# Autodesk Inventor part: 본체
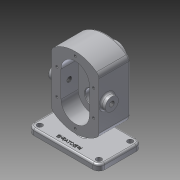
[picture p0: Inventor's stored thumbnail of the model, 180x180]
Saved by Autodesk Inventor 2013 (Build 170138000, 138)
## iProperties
Created: 2019-03
Part Number: 본체
Material: 알루미늄 6061
Document SubType Name: Modeling
Designer: Administrator
Density: 2.71 g/cm^3
Mass: 1193.14 g
Surface Area: 720.724 cm^2
Volume: 440.275 cm^3
Author: Administrator
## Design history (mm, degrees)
sketch "스케치2"
  geometry: L1 (-40, 60)-(40, 60); L2 (40, 60)-(40, -60); L3 (40, -60)-(-40, -60); L4 (-40, -60)-(-40, 60); A1 r 60 centre (0, 0) between (-40, -44.721) and (40, -44.721); A2 r 60 centre (0, 0) between (40, 44.721) and (-40, 44.721); 3 further points
  constraints: 8 end point, 5 point on circle, 4 point on line, 2 centre point, 2 midpoint, 2 parallel, 1 coincident, 1 horizontal, 1 horizontal alignment, 1 perpendicular, 1 vertical alignment
  dimensions: "d0" = 80 distance between parallel lines of L2 L4; "d2" = 120 distance of L3.end L1.start; "d5" = 60 radius of A2; "d6" = 60 radius of A1
extrude "돌출1" new body sketch "스케치2" distance "d7" = 53; taper "d8" = 0 deg
sketch "스케치3"
  geometry: L1 (-40, 44.721)-(-40, -44.721) reference; L2 (-24, 22)-(-24, -22); L3 (24, -22)-(24, 22); A1 r 60 centre (0, 0) between (40, 44.721) and (-40, 44.721) reference; A2 r 24 centre (0, 22) between (24, 22) and (-24, 22); A3 r 24 centre (0, -22) between (-24, -22) and (24, -22)
  constraints: 4 end point, 4 point on circle, 2 centre point, 2 parallel, 2 tangent, 2 vertical alignment
  dimensions: "d9" = 24 radius of A2; "d10" = 24 radius of A3; "d11" = 44 distance of A3.centre A2.centre; "d12" = 22 distance of A1.centre A2.centre
extrude "돌출2" cut sketch "스케치3" distance "d13" = 29; taper "d14" = 0 deg
sketch "스케치4"
  geometry: C1 r 12.5 at (0, 22); C2 r 12.5 at (0, -22); A1 r 24 centre (0, -22) between (-24, -22) and (24, -22) reference; A2 r 24 centre (0, 22) between (24, 22) and (-24, 22) reference; 1 further point
  constraints: 2 centre point, 2 coincident
  dimensions: "d15" = 12.5 radius of C1; "d16" = 12.5 radius of C2
extrude "돌출3" cut sketch "스케치4" distance "d17" = 15; taper "d18" = 0 deg
sketch "스케치5"
  geometry: C1 r 12.5 at (0, 0) reference; C2 r 8.5 at (0, 0); 1 further point
  constraints: 1 centre point, 1 coincident
  dimensions: "d19" = 8.5 radius of C2
extrude "돌출4" cut sketch "스케치5" stored distance "d20" = 15; taper "d21" = 0 deg
sketch "스케치6"
  geometry: C1 r 8.5 at (0, 22) reference; C2 r 19 at (0, 22)
  constraints: 1 centre point, 1 coincident
  dimensions: "d22" = 19 radius of C2
extrude "돌출5" join sketch "스케치6" distance "d23" = 17; taper "d24" = 0 deg
sketch "스케치7"
  geometry: L1 (3, -17)-(41, -17) reference; L2 (30.5, 9)-(30.5, -17) reference; L3 (13.5, 9)-(13.5, -17) reference; L4 (22, 8.572)-(22, -17); L5 (22, -9.7)-(35.5, -9.7); L6 (36, -10.2)-(36, -16.3); L7 (36, -16.3)-(22, -16.3); L8 (22, -16.3)-(22, -9.7); L9 (36, -16.3)-(36.404, -17); L10 (36, -16.3)-(39.088, -16.3); L11 (36, -16.3)-(36, -19.794); A1 r 0.5 centre (35.5, -10.2) between (36, -10.2) and (35.5, -9.7); 2 further points
  constraints: 16 end point, 4 point on line, 3 parallel, 2 horizontal, 2 perpendicular, 2 point on circle, 2 tangent, 1 centre point, 1 midpoint
  dimensions: "d25" = 6.6 distance of point (36, -9.7) L6.end; "d28" = 7.3 distance from line of L4.end L5; "d30" = 28 diameter of L6 L4; "d31" = 30 deg angle of L11 L9; "d32" = 0.5 radius of A1
revolve "회전1" sketch "스케치7" stored, may be unused: angle "d33" = 90 deg
sketch "스케치8"
  geometry: C1 r 12.5 at (0, 22) reference; A1 r 24 centre (0, -22) between (-24, -22) and (24, -22) reference; A2 r 24 centre (0, 22) between (24, 22) and (-24, 22) reference; A3 r 31 centre (0, 22) between (0, 53) and (-31, 22); A4 r 31 centre (0, -22) between (31, -22) and (0, -53); 2 further points
  constraints: 6 point on circle, 4 vertical alignment, 2 centre point, 2 coincident, 2 horizontal alignment
  dimensions: "d34" = 31 radius of A3; "d35" = 31 radius of A4
hole "구멍1" sketch "스케치8" at (0, 53), (-31, 22), (31, 22), (31, -22), (0, -53), (-31, -22) diameter "d36" = 4.134; stored, may be unused: countersink angle "d40" = 90 deg, drill point angle "d42" = 118 deg; dims "d37" = 10, "d38" = 4, "d39" = 2, "d41" = 12
sketch "스케치9"
  geometry: L1 (0, 0)-(0, 89.443) reference; L2 (-53, 0)-(-53, 89.443) reference; C1 r 11 at (-39, 44.721); 2 further points
  constraints: 1 centre point, 1 horizontal alignment, 1 midpoint
  dimensions: "d43" = 22 diameter of C1; "d45" = 14 distance from line of L2 C1.centre
extrude "돌출6" join sketch "스케치9" distance "d46" = 8; taper "d47" = 0 deg
sketch "스케치10"
  geometry: C1 r 11 at (0, 0) reference; 1 further point
sketch "스케치11"
  geometry: C1 r 11 at (0, 0) reference; 1 further point
hole "구멍2" sketch "스케치11" at (0, 0) diameter "d48" = 8.376; stored, may be unused: countersink angle "d52" = 90 deg, drill point angle "d54" = 118 deg; dims "d49" = 30, "d50" = 4, "d51" = 2, "d53" = 12
hole "구멍3" sketch "스케치10" diameter "d55" = 8.376; stored, may be unused: countersink angle "d59" = 90 deg, drill point angle "d61" = 118 deg; dims "d56" = 100, "d57" = 4, "d58" = 2, "d60" = 12
node "작업 평면2"
sketch "스케치12"
  geometry: L1 (40, 53)-(-40, 53) reference; L2 (40, 0)-(-40, 0) reference; L3 (-40, 50)-(-48, 50) reference; L4 (-40, 28)-(-48, 28) reference; L5 (-40, 28)-(-48, 28) reference; L6 (-40, 28)-(-48, 28) reference; L7 (-44, 28)-(-44, 50); L8 (-60, 0)-(60, 0); L9 (60, 0)-(60, 73); L10 (60, 73)-(-60, 73); L11 (-60, 73)-(-60, 0); 3 further points
  constraints: 10 end point, 4 midpoint, 2 coincident, 2 parallel, 1 horizontal, 1 perpendicular
  dimensions: "d63" = 120 distance between parallel lines of L9 L11; "d65" = 73 distance of L10.end L8.start
extrude "돌출7" join sketch "스케치12" distance "d66" = 10; taper "d67" = 0 deg
sketch "스케치13"
  geometry: L1 (60, 0)-(-60, 0) reference; L2 (-60, 0)-(-60, -73) reference; L3 (-60, -73)-(60, -73) reference; L4 (-6, -43)-(6, -43); L5 (6, -43)-(6, 0); L6 (6, 0)-(-6, 0); L7 (-6, 0)-(-6, -43); 4 further points
  constraints: 8 end point, 2 coincident, 2 midpoint, 2 parallel, 1 horizontal, 1 perpendicular, 1 other
  dimensions: "d68" = 12 distance of L6.end L5.end; "d69" = 43 distance of L5.end L4.end; "d70" = 10 distance from line of L3 point (0, -63); "d71" = 60 distance from line of L2 point (0, -63)
feature "엠보싱1" dims "d0" = 80, "d2" = 120, "d5" = 60, "d6" = 60, "d14" = 0, "d72" = 0.5, "d73" = 0
extrude "돌출8" join sketch "스케치13" stored distance "d74" = 10; taper "d75" = 0 deg
fillet "모깎기1" dims "d76" = 10
sketch "스케치14"
  geometry: A1 r 10 centre (-50, -63) between (-60, -63) and (-50, -73) reference; A2 r 10 centre (50, -63) between (50, -73) and (60, -63) reference; A3 r 10 centre (50, -10) between (60, -10) and (50, 0) reference; A4 r 10 centre (-50, -10) between (-50, 0) and (-60, -10) reference; 1 further point
hole "구멍4" sketch "스케치14" at (-50, -63), (-50, -10), (50, -63), (50, -10) diameter "d77" = 9; stored, may be unused: countersink angle "d81" = 90 deg, drill point angle "d83" = 118 deg; dims "d78" = 10, "d79" = 4, "d80" = 2, "d82" = 12
chamfer "모따기1" distance "d84" = 1; stored, may be unused: second distance "d85" = 2, angle "d86" = 45 deg
fillet "모깎기2" dims "d87" = 3
fillet "모깎기3" dims "d88" = 3, "d90" = 10
fillet "모깎기4" dims "d89" = 3
fillet "모깎기5" dims "d91" = 3
node "솔리드1"
mirror "대칭1"
node "작업 평면1"
other parameters: "d62" = -78
